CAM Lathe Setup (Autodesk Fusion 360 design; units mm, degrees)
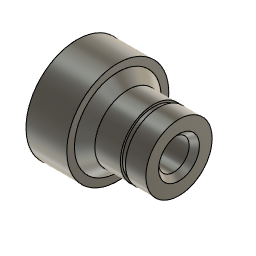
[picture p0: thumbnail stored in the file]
sketch "Sketch1" plane through (0, 0, 0) normal (0, 1, 0) x axis (1, 0, 0)
  line L1 (63.5, 0) -> (0, 0)
  line L2 (38.1, 0) -> (0, 0)
  line L3 (38.1, -9.525) -> (38.1, 0)
  line L4 (60.325, -9.525) -> (38.1, -9.525)
  line L5 (63.5, -12.7) -> (60.325, -9.525)
  line L6 (63.5, -20.6375) -> (63.5, -12.7)
  line L7 (50.8, -20.6375) -> (63.5, -20.6375)
  line L8 (50.8, -19.3675) -> (50.8, -20.6375)
  line L9 (47.625, -19.3675) -> (50.8, -19.3675)
  line L10 (47.625, -20.6375) -> (47.625, -19.3675)
  line L11 (31.75, -20.6375) -> (47.625, -20.6375)
  line L12 (25.4, -26.9875) -> (31.75, -20.6375)
  line L13 (25.4, -31.75) -> (25.4, -26.9875)
  line L14 (0, -31.75) -> (25.4, -31.75)
  line L15 (0, 0) -> (0, -31.75)
  point P1 (0, 0)
  point P2 (0, 0)
  point P4 (0, 0)
  point P5 (38.1, 0)
  point P18 (0, 0)
  point P3 (63.5, 0)
  point P7 (60.325, -9.525)
  point P8 (63.5, -12.7)
  point P10 (50.8, -20.6375)
  point P11 (50.8, -19.3675)
  point P9 (63.5, -20.6375)
  point P14 (31.75, -20.6375)
  point P15 (25.4, -26.9875)
  point P16 (25.4, -31.75)
  point P17 (0, -31.75)
  coincident P1 P2
  horizontal L1
  coincident P1 P4
  coincident L1 P5
  parallel L1 L2
  perpendicular L2 L3
  perpendicular L3 L4
  perpendicular L4 L6
  perpendicular L6 L7
  perpendicular L7 L8
  perpendicular L8 L9
  perpendicular L9 L10
  perpendicular L10 L11
  perpendicular L11 L13
  perpendicular L13 L14
  coincident P1 P18
  perpendicular L1 L15
  coincident P3 L6
  collinear L7 L11
  dimension "d1" distance P2 P3 = 63.5
  dimension "d2" angle L4 L5 = 45
  dimension "d3" distance P7 P8 = 3.175
  dimension "d4" = 19.05
  dimension "d5" distance L3 L6 = 25.4
  dimension "d6" = 41.275
  dimension "d7" distance L8 L10 = 3.175
  dimension "d8" distance P10 P11 = 1.27
  dimension "d9" distance P9 P10 = 12.7
  dimension "d10" angle L11 L12 = 45
  dimension "d11" distance P14 P15 = 6.35
  dimension "d12" = 63.5
  dimension "d13" distance P16 P17 = 25.4
revolve "Revolve1" sketch "Sketch1" AlongAngle 360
